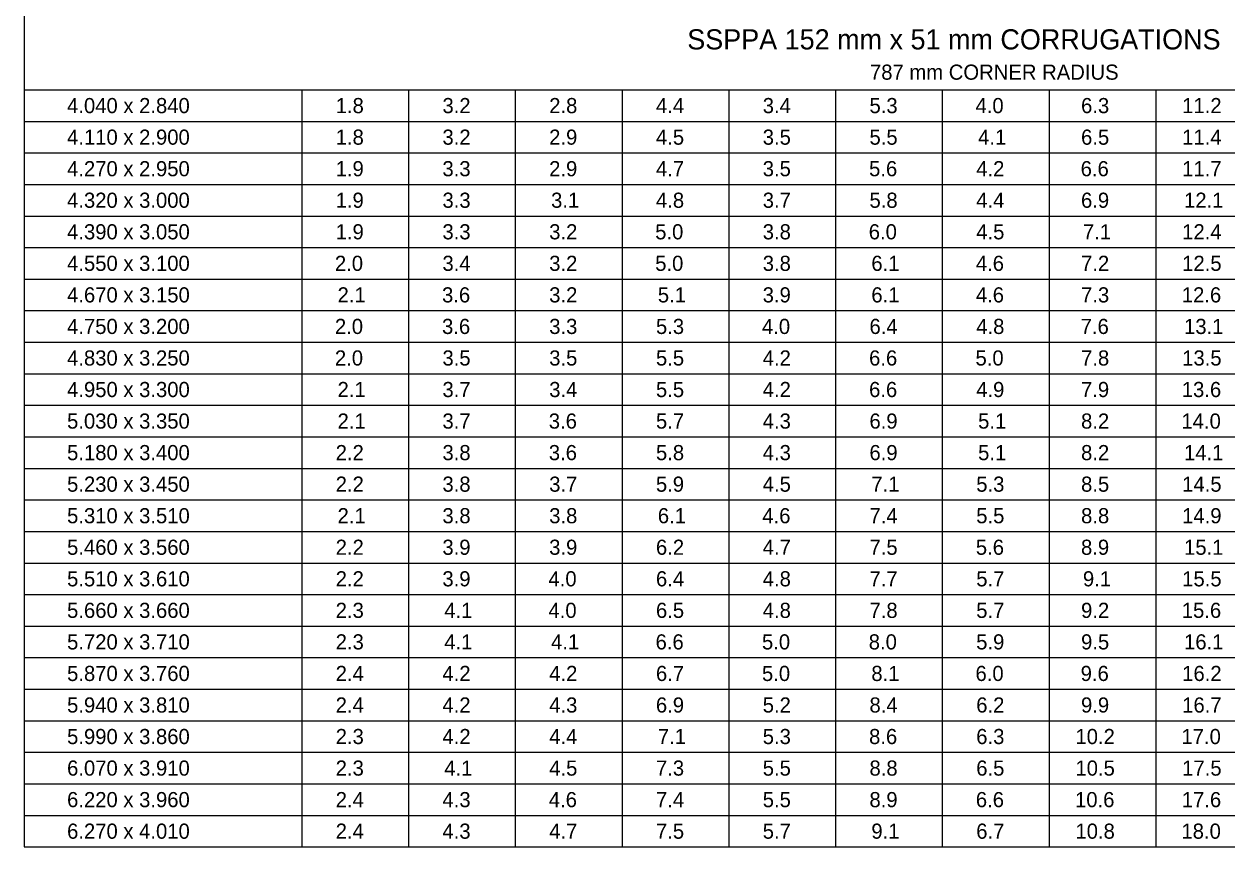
# Model space of a CAD drawing. Extents: x 49991.4 to 50047.6, y 49987.6 to 50011.4.
# Drawn here: x 50031.96 to 50036.728, y 50003.598 to 50006.859 of the extents above; entities that cross this region are included whole.
import ezdxf

# ---------------------------------------------------------------- set-up
doc = ezdxf.new("R2010")
doc.units = 0
doc.layers.add('Level 5', color=7, linetype='Continuous')

msp = doc.modelspace()

# ---------------------------------------------------------------- linework, layer by layer
at = {"layer": 'Level 5'}
for p, q in [((50031.9605, 50011.0583), (50031.9605, 50003.5983)), ((50031.9605, 50006.5983), (50039.8305, 50006.5983)), ((50033.0609, 50006.5983), (50033.0609, 50003.5983)), ((50033.484, 50006.5983), (50033.484, 50003.5983)), ((50033.9071, 50006.5983), (50033.9071, 50003.5983)), ((50034.3302, 50006.5983), (50034.3302, 50003.5983)), ((50034.7533, 50006.5983), (50034.7533, 50003.5983)), ((50035.1764, 50006.5983), (50035.1764, 50003.5983)), ((50035.5995, 50006.5983), (50035.5995, 50003.5983)), ((50036.0226, 50006.5983), (50036.0226, 50003.5983)), ((50036.4457, 50006.5983), (50036.4457, 50003.5983)), ((50031.9605, 50006.4733), (50039.8305, 50006.4733)), ((50031.9605, 50006.3483), (50039.8305, 50006.3483)), ((50031.9605, 50006.2233), (50039.8305, 50006.2233)), ((50031.9605, 50006.0983), (50039.8305, 50006.0983)), ((50031.9605, 50005.9733), (50039.8305, 50005.9733)), ((50031.9605, 50005.8483), (50039.8305, 50005.8483)), ((50031.9605, 50005.7233), (50039.8305, 50005.7233)), ((50031.9605, 50005.5983), (50039.8305, 50005.5983)), ((50031.9605, 50005.4733), (50039.8305, 50005.4733)), ((50031.9605, 50005.3483), (50039.8305, 50005.3483)), ((50031.9605, 50005.2233), (50039.8305, 50005.2233)), ((50031.9605, 50005.0983), (50039.8305, 50005.0983)), ((50031.9605, 50004.9733), (50039.8305, 50004.9733)), ((50031.9605, 50004.8483), (50039.8305, 50004.8483)), ((50031.9605, 50004.7233), (50039.8305, 50004.7233)), ((50031.9605, 50004.5983), (50039.8305, 50004.5983)), ((50031.9605, 50004.4733), (50039.8305, 50004.4733)), ((50031.9605, 50004.3483), (50039.8305, 50004.3483)), ((50031.9605, 50004.2233), (50039.8305, 50004.2233)), ((50031.9605, 50004.0983), (50039.8305, 50004.0983)), ((50031.9605, 50003.9733), (50039.8305, 50003.9733)), ((50031.9605, 50003.8483), (50039.8305, 50003.8483)), ((50031.9605, 50003.7233), (50039.8305, 50003.7233)), ((50031.9605, 50003.5983), (50039.8305, 50003.5983))]:
    msp.add_line(p, q, dxfattribs=at)

# ---------------------------------------------------------------- texts
for s, height, p in [('SSPPA 152 mm x 51 mm CORRUGATIONS', 0.0799, (50034.5888, 50006.7583)), ('787 mm CORNER RADIUS', 0.06, (50035.313, 50006.6383)), ('4.040 x 2.840', 0.06, (50032.131, 50006.5058)), ('1.8', 0.06, (50033.1955, 50006.5058)), ('3.2', 0.06, (50033.6186, 50006.5058)), ('2.8', 0.06, (50034.0417, 50006.5058)), ('4.4', 0.06, (50034.4648, 50006.5058)), ('3.4', 0.06, (50034.8879, 50006.5058)), ('5.3', 0.06, (50035.311, 50006.5058)), ('4.0', 0.06, (50035.7311, 50006.5058)), (' 6.3', 0.06, (50036.1272, 50006.5058)), ('11.2', 0.06, (50036.5503, 50006.5058)), ('4.110 x 2.900', 0.06, (50032.131, 50006.3808)), ('1.8', 0.06, (50033.1955, 50006.3808)), ('3.2', 0.06, (50033.6186, 50006.3808)), ('2.9', 0.06, (50034.0415, 50006.3808)), ('4.5', 0.06, (50034.4648, 50006.3808)), ('3.5', 0.06, (50034.8879, 50006.3808)), ('5.5', 0.06, (50035.311, 50006.3808)), ('4.1', 0.06, (50035.7415, 50006.3808)), (' 6.5', 0.06, (50036.1272, 50006.3808)), ('11.4', 0.06, (50036.5503, 50006.3808)), ('4.270 x 2.950', 0.06, (50032.131, 50006.2558)), ('1.9', 0.06, (50033.1953, 50006.2558)), ('3.3', 0.06, (50033.6186, 50006.2558)), ('2.9', 0.06, (50034.0415, 50006.2558)), ('4.7', 0.06, (50034.4648, 50006.2558)), ('3.5', 0.06, (50034.8879, 50006.2558)), ('5.6', 0.06, (50035.3094, 50006.2558)), ('4.2', 0.06, (50035.7341, 50006.2558)), (' 6.6', 0.06, (50036.1256, 50006.2558)), ('11.7', 0.06, (50036.5503, 50006.2558)), ('4.320 x 3.000', 0.06, (50032.131, 50006.1308)), ('1.9', 0.06, (50033.1953, 50006.1308)), ('3.3', 0.06, (50033.6186, 50006.1308)), ('3.1', 0.06, (50034.0491, 50006.1308)), ('4.8', 0.06, (50034.4648, 50006.1308)), ('3.7', 0.06, (50034.8879, 50006.1308)), ('5.8', 0.06, (50035.311, 50006.1308)), ('4.4', 0.06, (50035.7341, 50006.1308)), (' 6.9', 0.06, (50036.127, 50006.1308)), ('12.1', 0.06, (50036.5577, 50006.1308)), ('4.390 x 3.050', 0.06, (50032.131, 50006.0058)), ('1.9', 0.06, (50033.1953, 50006.0058)), ('3.3', 0.06, (50033.6186, 50006.0058)), ('3.2', 0.06, (50034.0417, 50006.0058)), ('5.0', 0.06, (50034.4618, 50006.0058)), ('3.8', 0.06, (50034.8879, 50006.0058)), ('6.0', 0.06, (50035.308, 50006.0058)), ('4.5', 0.06, (50035.7341, 50006.0058)), (' 7.1', 0.06, (50036.1346, 50006.0058)), ('12.4', 0.06, (50036.5503, 50006.0058)), ('4.550 x 3.100', 0.06, (50032.131, 50005.8808)), ('2.0', 0.06, (50033.1925, 50005.8808)), ('3.4', 0.06, (50033.6186, 50005.8808)), ('3.2', 0.06, (50034.0417, 50005.8808)), ('5.0', 0.06, (50034.4618, 50005.8808)), ('3.8', 0.06, (50034.8879, 50005.8808)), ('6.1', 0.06, (50035.3184, 50005.8808)), ('4.6', 0.06, (50035.7325, 50005.8808)), (' 7.2', 0.06, (50036.1272, 50005.8808)), ('12.5', 0.06, (50036.5503, 50005.8808)), ('4.670 x 3.150', 0.06, (50032.131, 50005.7558)), ('2.1', 0.06, (50033.2029, 50005.7558)), ('3.6', 0.06, (50033.617, 50005.7558)), ('3.2', 0.06, (50034.0417, 50005.7558)), ('5.1', 0.06, (50034.4722, 50005.7558)), ('3.9', 0.06, (50034.8877, 50005.7558)), ('6.1', 0.06, (50035.3184, 50005.7558)), ('4.6', 0.06, (50035.7325, 50005.7558)), (' 7.3', 0.06, (50036.1272, 50005.7558)), ('12.6', 0.06, (50036.5487, 50005.7558)), ('4.750 x 3.200', 0.06, (50032.131, 50005.6308)), ('2.0', 0.06, (50033.1925, 50005.6308)), ('3.6', 0.06, (50033.617, 50005.6308)), ('3.3', 0.06, (50034.0417, 50005.6308)), ('5.3', 0.06, (50034.4648, 50005.6308)), ('4.0', 0.06, (50034.8849, 50005.6308)), ('6.4', 0.06, (50035.311, 50005.6308)), ('4.8', 0.06, (50035.7341, 50005.6308)), (' 7.6', 0.06, (50036.1256, 50005.6308)), ('13.1', 0.06, (50036.5577, 50005.6308)), ('4.830 x 3.250', 0.06, (50032.131, 50005.5058)), ('2.0', 0.06, (50033.1925, 50005.5058)), ('3.5', 0.06, (50033.6186, 50005.5058)), ('3.5', 0.06, (50034.0417, 50005.5058)), ('5.5', 0.06, (50034.4648, 50005.5058)), ('4.2', 0.06, (50034.8879, 50005.5058)), ('6.6', 0.06, (50035.3094, 50005.5058)), ('5.0', 0.06, (50035.7311, 50005.5058)), (' 7.8', 0.06, (50036.1272, 50005.5058)), ('13.5', 0.06, (50036.5503, 50005.5058)), ('4.950 x 3.300', 0.06, (50032.131, 50005.3808)), ('2.1', 0.06, (50033.2029, 50005.3808)), ('3.7', 0.06, (50033.6186, 50005.3808)), ('3.4', 0.06, (50034.0417, 50005.3808)), ('5.5', 0.06, (50034.4648, 50005.3808)), ('4.2', 0.06, (50034.8879, 50005.3808)), ('6.6', 0.06, (50035.3094, 50005.3808)), ('4.9', 0.06, (50035.7339, 50005.3808)), (' 7.9', 0.06, (50036.127, 50005.3808)), ('13.6', 0.06, (50036.5487, 50005.3808)), ('5.030 x 3.350', 0.06, (50032.131, 50005.2558)), ('2.1', 0.06, (50033.2029, 50005.2558)), ('3.7', 0.06, (50033.6186, 50005.2558)), ('3.6', 0.06, (50034.0401, 50005.2558)), ('5.7', 0.06, (50034.4648, 50005.2558)), ('4.3', 0.06, (50034.8879, 50005.2558)), ('6.9', 0.06, (50035.3108, 50005.2558)), ('5.1', 0.06, (50035.7415, 50005.2558)), (' 8.2', 0.06, (50036.1272, 50005.2558)), ('14.0', 0.06, (50036.5473, 50005.2558)), ('5.180 x 3.400', 0.06, (50032.131, 50005.1308)), ('2.2', 0.06, (50033.1955, 50005.1308)), ('3.8', 0.06, (50033.6186, 50005.1308)), ('3.6', 0.06, (50034.0401, 50005.1308)), ('5.8', 0.06, (50034.4648, 50005.1308)), ('4.3', 0.06, (50034.8879, 50005.1308)), ('6.9', 0.06, (50035.3108, 50005.1308)), ('5.1', 0.06, (50035.7415, 50005.1308)), (' 8.2', 0.06, (50036.1272, 50005.1308)), ('14.1', 0.06, (50036.5577, 50005.1308)), ('5.230 x 3.450', 0.06, (50032.131, 50005.0058)), ('2.2', 0.06, (50033.1955, 50005.0058)), ('3.8', 0.06, (50033.6186, 50005.0058)), ('3.7', 0.06, (50034.0417, 50005.0058)), ('5.9', 0.06, (50034.4646, 50005.0058)), ('4.5', 0.06, (50034.8879, 50005.0058)), ('7.1', 0.06, (50035.3184, 50005.0058)), ('5.3', 0.06, (50035.7341, 50005.0058)), (' 8.5', 0.06, (50036.1272, 50005.0058)), ('14.5', 0.06, (50036.5503, 50005.0058)), ('5.310 x 3.510', 0.06, (50032.131, 50004.8808)), ('2.1', 0.06, (50033.2029, 50004.8808)), ('3.8', 0.06, (50033.6186, 50004.8808)), ('3.8', 0.06, (50034.0417, 50004.8808)), ('6.1', 0.06, (50034.4722, 50004.8808)), ('4.6', 0.06, (50034.8863, 50004.8808)), ('7.4', 0.06, (50035.311, 50004.8808)), ('5.5', 0.06, (50035.7341, 50004.8808)), (' 8.8', 0.06, (50036.1272, 50004.8808)), ('14.9', 0.06, (50036.5501, 50004.8808)), ('5.460 x 3.560', 0.06, (50032.131, 50004.7558)), ('2.2', 0.06, (50033.1955, 50004.7558)), ('3.9', 0.06, (50033.6184, 50004.7558)), ('3.9', 0.06, (50034.0415, 50004.7558)), ('6.2', 0.06, (50034.4648, 50004.7558)), ('4.7', 0.06, (50034.8879, 50004.7558)), ('7.5', 0.06, (50035.311, 50004.7558)), ('5.6', 0.06, (50035.7325, 50004.7558)), (' 8.9', 0.06, (50036.127, 50004.7558)), ('15.1', 0.06, (50036.5577, 50004.7558)), ('5.510 x 3.610', 0.06, (50032.131, 50004.6308)), ('2.2', 0.06, (50033.1955, 50004.6308)), ('3.9', 0.06, (50033.6184, 50004.6308)), ('4.0', 0.06, (50034.0387, 50004.6308)), ('6.4', 0.06, (50034.4648, 50004.6308)), ('4.8', 0.06, (50034.8879, 50004.6308)), ('7.7', 0.06, (50035.311, 50004.6308)), ('5.7', 0.06, (50035.7341, 50004.6308)), (' 9.1', 0.06, (50036.1346, 50004.6308)), ('15.5', 0.06, (50036.5503, 50004.6308)), ('5.660 x 3.660', 0.06, (50032.131, 50004.5058)), ('2.3', 0.06, (50033.1955, 50004.5058)), ('4.1', 0.06, (50033.626, 50004.5058)), ('4.0', 0.06, (50034.0387, 50004.5058)), ('6.5', 0.06, (50034.4648, 50004.5058)), ('4.8', 0.06, (50034.8879, 50004.5058)), ('7.8', 0.06, (50035.311, 50004.5058)), ('5.7', 0.06, (50035.7341, 50004.5058)), (' 9.2', 0.06, (50036.1272, 50004.5058)), ('15.6', 0.06, (50036.5487, 50004.5058)), ('5.720 x 3.710', 0.06, (50032.131, 50004.3808)), ('2.3', 0.06, (50033.1955, 50004.3808)), ('4.1', 0.06, (50033.626, 50004.3808)), ('4.1', 0.06, (50034.0491, 50004.3808)), ('6.6', 0.06, (50034.4632, 50004.3808)), ('5.0', 0.06, (50034.8849, 50004.3808)), ('8.0', 0.06, (50035.308, 50004.3808)), ('5.9', 0.06, (50035.7339, 50004.3808)), (' 9.5', 0.06, (50036.1272, 50004.3808)), ('16.1', 0.06, (50036.5577, 50004.3808)), ('5.870 x 3.760', 0.06, (50032.131, 50004.2558)), ('2.4', 0.06, (50033.1955, 50004.2558)), ('4.2', 0.06, (50033.6186, 50004.2558)), ('4.2', 0.06, (50034.0417, 50004.2558)), ('6.7', 0.06, (50034.4648, 50004.2558)), ('5.0', 0.06, (50034.8849, 50004.2558)), ('8.1', 0.06, (50035.3184, 50004.2558)), ('6.0', 0.06, (50035.7311, 50004.2558)), (' 9.6', 0.06, (50036.1256, 50004.2558)), ('16.2', 0.06, (50036.5503, 50004.2558)), ('5.940 x 3.810', 0.06, (50032.131, 50004.1308)), ('2.4', 0.06, (50033.1955, 50004.1308)), ('4.2', 0.06, (50033.6186, 50004.1308)), ('4.3', 0.06, (50034.0417, 50004.1308)), ('6.9', 0.06, (50034.4646, 50004.1308)), ('5.2', 0.06, (50034.8879, 50004.1308)), ('8.4', 0.06, (50035.311, 50004.1308)), ('6.2', 0.06, (50035.7341, 50004.1308)), (' 9.9', 0.06, (50036.127, 50004.1308)), ('16.7', 0.06, (50036.5503, 50004.1308)), ('5.990 x 3.860', 0.06, (50032.131, 50004.0058)), ('2.3', 0.06, (50033.1955, 50004.0058)), ('4.2', 0.06, (50033.6186, 50004.0058)), ('4.4', 0.06, (50034.0417, 50004.0058)), ('7.1', 0.06, (50034.4722, 50004.0058)), ('5.3', 0.06, (50034.8879, 50004.0058)), ('8.6', 0.06, (50035.3094, 50004.0058)), ('6.3', 0.06, (50035.7341, 50004.0058)), ('10.2', 0.06, (50036.1272, 50004.0058)), ('17.0', 0.06, (50036.5473, 50004.0058)), ('6.070 x 3.910', 0.06, (50032.131, 50003.8808)), ('2.3', 0.06, (50033.1955, 50003.8808)), ('4.1', 0.06, (50033.626, 50003.8808)), ('4.5', 0.06, (50034.0417, 50003.8808)), ('7.3', 0.06, (50034.4648, 50003.8808)), ('5.5', 0.06, (50034.8879, 50003.8808)), ('8.8', 0.06, (50035.311, 50003.8808)), ('6.5', 0.06, (50035.7341, 50003.8808)), ('10.5', 0.06, (50036.1272, 50003.8808)), ('17.5', 0.06, (50036.5503, 50003.8808)), ('6.220 x 3.960', 0.06, (50032.131, 50003.7558)), ('2.4', 0.06, (50033.1955, 50003.7558)), ('4.3', 0.06, (50033.6186, 50003.7558)), ('4.6', 0.06, (50034.0401, 50003.7558)), ('8.9', 0.06, (50035.3108, 50003.7558)), ('6.6', 0.06, (50035.7325, 50003.7558)), ('10.6', 0.06, (50036.1256, 50003.7558)), ('17.6', 0.06, (50036.5487, 50003.7558)), ('7.4', 0.06, (50034.4648, 50003.7558)), ('5.5', 0.06, (50034.8879, 50003.7558)), ('6.270 x 4.010', 0.06, (50032.131, 50003.6308)), ('2.4', 0.06, (50033.1955, 50003.6308)), ('4.3', 0.06, (50033.6186, 50003.6308)), ('4.7', 0.06, (50034.0417, 50003.6308)), ('7.5', 0.06, (50034.4648, 50003.6308)), ('5.7', 0.06, (50034.8879, 50003.6308)), ('9.1', 0.06, (50035.3184, 50003.6308)), ('6.7', 0.06, (50035.7341, 50003.6308)), ('10.8', 0.06, (50036.1272, 50003.6308)), ('18.0', 0.06, (50036.5473, 50003.6308))]:
    msp.add_text(s, height=height, dxfattribs=at).set_placement(p)

doc.saveas('drawing.dxf')
